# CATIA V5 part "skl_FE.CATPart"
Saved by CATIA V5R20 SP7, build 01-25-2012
Part number: skl_FE
Publications: "Axe_EF_E", "Axe_EF_F", "EF", "Point F", "Point E", "Plan.1"
Bounding box of the stored display mesh (mm): x 0 to 10, y -127.331 to 124.167, z 63.473 to 95.272
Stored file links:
  U:\IAO-Thinkmotion\TRAVAIL A RENDRE\skl_FE.CATPart
  U:\IAO-Thinkmotion\TRAVAIL A RENDRE\skl_levier2bras.CATProduct
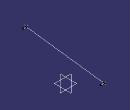
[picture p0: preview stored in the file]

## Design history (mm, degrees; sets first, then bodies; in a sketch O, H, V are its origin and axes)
Set1
  DatumPoint1 "Point F": linked copy from another document
  DatumPoint2 "Point E": linked copy from another document
  Plane1: linked copy from another document
Set2
  Line1 "EF": type PtPt, FirstPoint DatumPoint1, SecondPoint DatumPoint2
  Line2 "Axe_EF_F": type Normal, RefPoint DatumPoint1, RefSkin Plane1, Start 0, End 10
  Line3 "Axe_EF_E": type Normal, RefPoint DatumPoint2, RefSkin Plane1, Start 0, End 10
Body1 (main body)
